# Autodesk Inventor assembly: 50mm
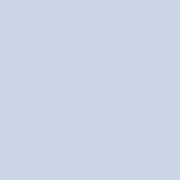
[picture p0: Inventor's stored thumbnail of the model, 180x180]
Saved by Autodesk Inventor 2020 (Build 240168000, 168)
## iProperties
Created: 2020-11
Part Number: 50mm
Document SubType Name: Assembly
Designer: Yolande
Author: Yolande
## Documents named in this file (1)
- D:\Drawing Division\3. Revit Family Files\2. Kraft\50mm.iam
